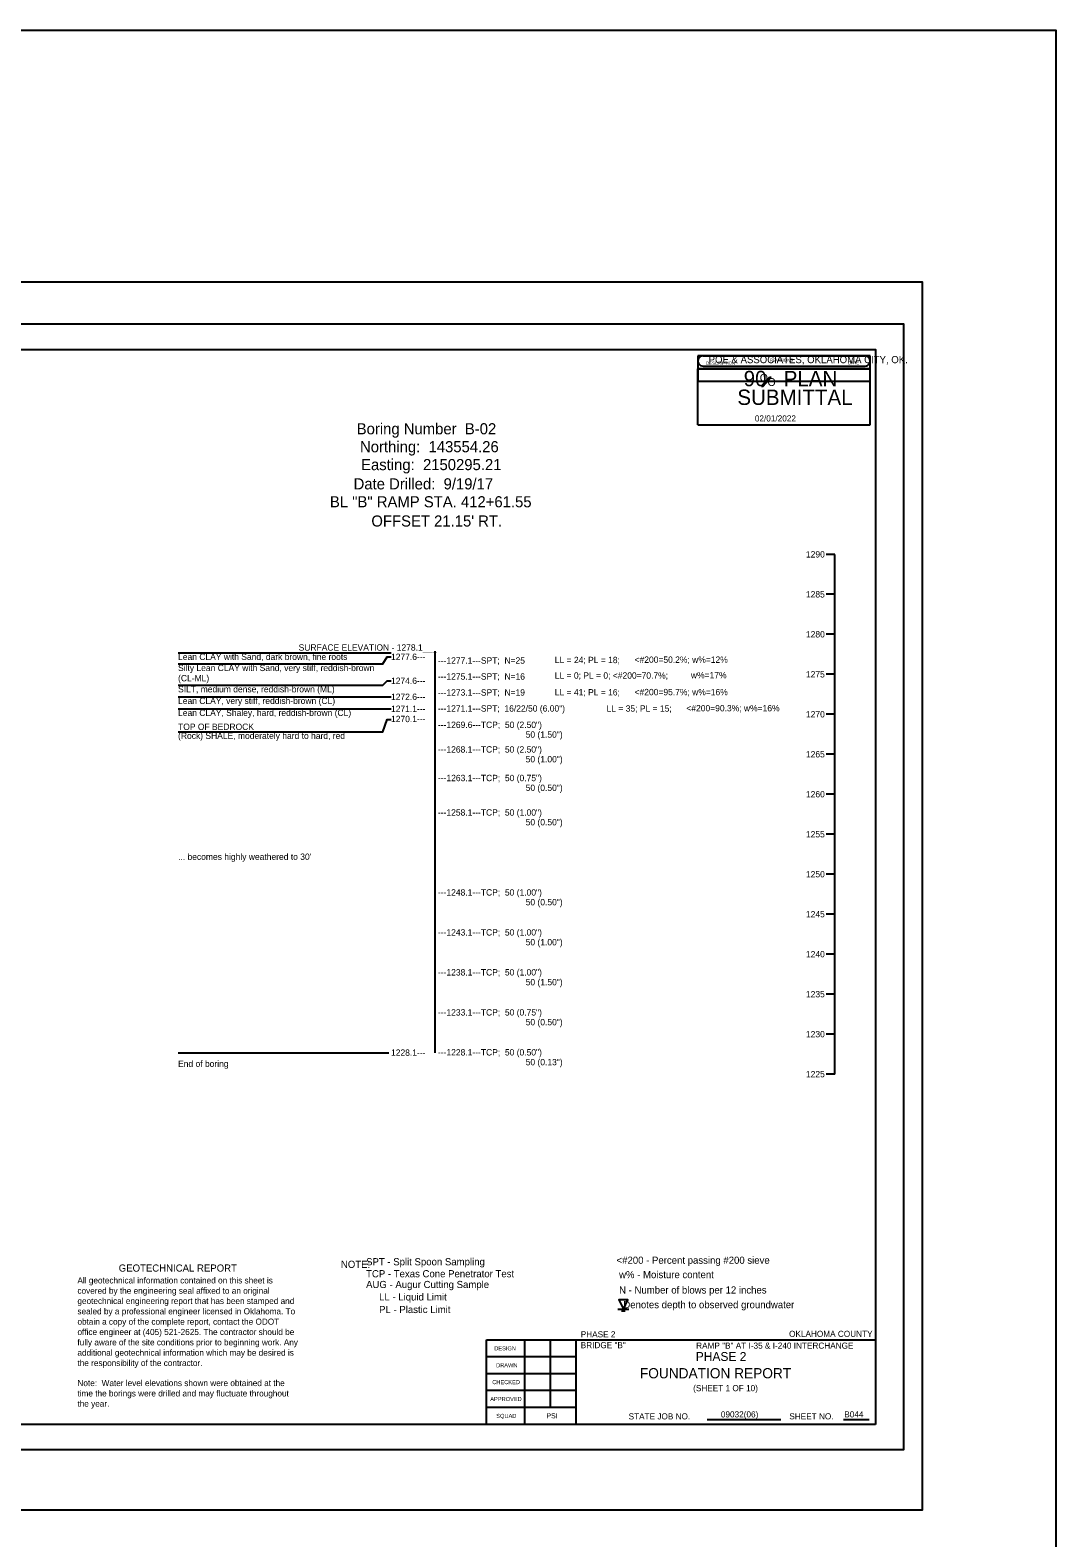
# Model space of a CAD drawing. Extents: x 2150162 to 2150245, y 143729 to 143865.
# Drawn here: x 2150183.36 to 2150203.4, y 143835.6 to 143865.06 of the extents above; entities that cross this region are included whole.
import ezdxf

# ---------------------------------------------------------------- set-up
doc = ezdxf.new("R2010")
doc.units = 0
for name, color, linetype in [('Default', 7, 'Continuous'), ('S', 7, 'Continuous'), ('SHT_Plot_Shape_Full', 7, 'Continuous'), ('SHT_Plot_Shape_Half', 7, 'Continuous'), ('SHT_Sheet_Border', 7, 'Continuous'), ('SHT_Stamp_90_Submit', 7, 'Continuous'), ('SHT_Stamp_Rev_Block', 7, 'Continuous'), ('SHT_Standard_Sheet_Lines', 7, 'Continuous'), ('SHT_Standard_Sheet_Txt', 7, 'Continuous'), ('T', 7, 'Continuous'), ('T-Title', 7, 'Continuous'), ('Text', 7, 'Continuous')]:
    doc.layers.add(name, color=color, linetype=linetype)

# ---------------------------------------------------------------- blocks, each defined once
blk = doc.blocks.new('DGRFC_WTLEV1')
at = {"layer": 'Default'}
for points in [[(-0.0127, 0), (0.0127, 0)], [(0, 0), (0.0106, 0.0212), (-0.0106, 0.0212), (0, 0)], [(-0.0042, -0.0042), (0.0042, -0.0042)]]:
    blk.add_lwpolyline(points, dxfattribs=at)

msp = doc.modelspace()

# ---------------------------------------------------------------- linework, layer by layer
at = {"layer": 'Default'}
for p, q in [((2150199.086, 143844.663), (2150199.086, 143854.819)), ((2150190.373, 143845.074), (2150186.253, 143845.074))]:
    msp.add_line(p, q, dxfattribs=at)
for points in [[(2150199.086, 143854.819), (2150198.919, 143854.819)], [(2150199.086, 143854.038), (2150198.919, 143854.038)], [(2150199.086, 143853.257), (2150198.919, 143853.257)], [(2150186.253, 143852.896), (2150190.419, 143852.896)], [(2150186.253, 143852.679), (2150190.253, 143852.679), (2150190.336, 143852.817), (2150190.419, 143852.817)], [(2150191.27, 143852.924), (2150191.27, 143845.076)], [(2150199.086, 143852.475), (2150198.919, 143852.475)], [(2150186.253, 143852.262), (2150186.419, 143852.262), (2150190.253, 143852.262), (2150190.336, 143852.349), (2150190.419, 143852.349)], [(2150186.253, 143852.036), (2150190.419, 143852.036)], [(2150186.253, 143851.802), (2150190.419, 143851.802)], [(2150186.253, 143851.354), (2150186.419, 143851.354), (2150190.253, 143851.354), (2150190.336, 143851.592), (2150190.419, 143851.592)], [(2150199.086, 143851.694), (2150198.919, 143851.694)], [(2150199.086, 143850.913), (2150198.919, 143850.913)], [(2150199.086, 143850.132), (2150198.919, 143850.132)], [(2150199.086, 143849.35), (2150198.919, 143849.35)], [(2150199.086, 143848.569), (2150198.919, 143848.569)], [(2150199.086, 143847.788), (2150198.919, 143847.788)], [(2150199.086, 143847.007), (2150198.919, 143847.007)], [(2150199.086, 143846.225), (2150198.919, 143846.225)], [(2150199.086, 143845.444), (2150198.919, 143845.444)], [(2150199.086, 143844.663), (2150198.919, 143844.663)]]:
    msp.add_lwpolyline(points, dxfattribs=at)
at = {"layer": 'S'}
msp.add_lwpolyline([(2150203.404, 143784.341), (2150161.568, 143784.341), (2150161.568, 143865.061), (2150203.404, 143865.061)], close=True, dxfattribs=at)
at = {"layer": 'SHT_Plot_Shape_Full'}
msp.add_lwpolyline([(2150164.792, 143860.145), (2150200.792, 143860.145), (2150200.792, 143836.145), (2150164.792, 143836.145)], close=True, dxfattribs=at)
at = {"layer": 'SHT_Plot_Shape_Half'}
msp.add_lwpolyline([(2150166.429, 143859.32), (2150200.429, 143859.32), (2150200.429, 143837.32), (2150166.429, 143837.32)], close=True, dxfattribs=at)
at = {"layer": 'SHT_Sheet_Border'}
for p, q in [((2150192.279, 143837.82), (2150192.279, 143839.47)), ((2150192.279, 143839.47), (2150199.879, 143839.47)), ((2150194.029, 143837.82), (2150194.029, 143839.471))]:
    msp.add_line(p, q, dxfattribs=at)
msp.add_lwpolyline([(2150199.879, 143837.82), (2150168.379, 143837.82), (2150168.379, 143858.82), (2150199.879, 143858.82)], close=True, dxfattribs=at)
at = {"layer": 'SHT_Stamp_90_Submit'}
for p, q in [((2150196.51, 143858.696), (2150199.676, 143858.696)), ((2150196.41, 143858.446), (2150199.776, 143858.446)), ((2150196.41, 143857.347), (2150196.41, 143858.446)), ((2150196.51, 143858.496), (2150199.676, 143858.496)), ((2150197.653, 143858.108), (2150197.809, 143858.281)), ((2150197.671, 143858.108), (2150197.827, 143858.281)), ((2150197.676, 143858.108), (2150197.832, 143858.281)), ((2150197.684, 143858.108), (2150197.839, 143858.281)), ((2150197.809, 143858.281), (2150197.839, 143858.281)), ((2150199.776, 143857.347), (2150199.776, 143858.446)), ((2150197.653, 143858.108), (2150197.684, 143858.108)), ((2150196.41, 143857.347), (2150199.776, 143857.347))]:
    msp.add_line(p, q, dxfattribs=at)
for centre, start, end in [((2150196.51, 143858.596), 89.9952, 270), ((2150199.676, 143858.596), 270, 90.0048)]:
    msp.add_arc(centre, 0.1, start, end, dxfattribs=at)
at = {"layer": 'SHT_Stamp_Rev_Block'}
for p, q in [((2150196.41, 143858.696), (2150196.41, 143858.196)), ((2150199.776, 143858.696), (2150196.41, 143858.696)), ((2150199.776, 143858.196), (2150199.776, 143858.696)), ((2150199.776, 143858.446), (2150196.41, 143858.446)), ((2150199.776, 143858.196), (2150196.41, 143858.196))]:
    msp.add_line(p, q, dxfattribs=at)
at = {"layer": 'SHT_Standard_Sheet_Lines'}
for p, q in [((2150193.029, 143837.82), (2150193.029, 143839.471)), ((2150193.529, 143838.15), (2150193.529, 143839.471)), ((2150196.59, 143837.916), (2150198.03, 143837.917)), ((2150199.255, 143837.916), (2150199.757, 143837.917))]:
    msp.add_line(p, q, dxfattribs=at)
for points in [[(2150194.029, 143839.14), (2150192.279, 143839.14)], [(2150194.029, 143838.81), (2150192.279, 143838.81)], [(2150194.029, 143838.48), (2150192.279, 143838.48)], [(2150194.029, 143838.15), (2150192.279, 143838.15)]]:
    msp.add_lwpolyline(points, dxfattribs=at)

# ---------------------------------------------------------------- block references
at = {"layer": 'Default', "xscale": 8.503919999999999, "yscale": 8.503919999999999}
msp.add_blockref('DGRFC_WTLEV1', (2150194.954, 143840.072), dxfattribs=at)

# ---------------------------------------------------------------- texts
at = {"layer": 'Default'}
for s, height, p in [('Boring Number  B-02', 0.217, (2150189.744, 143857.164)), ('Northing:  143554.26', 0.217, (2150189.808, 143856.814)), ('Easting:  2150295.21', 0.217, (2150189.829, 143856.464)), ('Date Drilled:  9/19/17', 0.217, (2150189.683, 143856.088)), ('BL "B" RAMP STA. 412+61.55', 0.217, (2150189.22, 143855.738)), ("OFFSET 21.15' RT.", 0.217, (2150190.03, 143855.362)), ('1290', 0.124, (2150198.521, 143854.757)), ('1285', 0.124, (2150198.521, 143853.976)), ('1280', 0.124, (2150198.521, 143853.195)), ('SURFACE ELEVATION - 1278.1___', 0.124, (2150188.609, 143852.937)), ('Silty Lean CLAY with Sand, very stiff, reddish-brown', 0.124, (2150186.253, 143852.538)), ('Lean CLAY with Sand, dark brown, fine roots', 0.124, (2150186.253, 143852.755)), ('1277.6---', 0.124, (2150190.414, 143852.755)), ('---1277.1---SPT;  N=25', 0.124, (2150191.331, 143852.683)), ('LL = 24; PL = 18;', 0.124, (2150193.614, 143852.693)), ('<#200=50.2%; w%=12%', 0.124, (2150195.173, 143852.699)), ('(CL-ML)', 0.124, (2150186.253, 143852.338)), ('1274.6---', 0.124, (2150190.414, 143852.287)), ('---1275.1---SPT;  N=16', 0.124, (2150191.331, 143852.371)), ('LL = 0; PL = 0; <#200=70.7%;', 0.124, (2150193.614, 143852.39)), ('w%=17%', 0.124, (2150196.274, 143852.396)), ('1275', 0.124, (2150198.521, 143852.413)), ('SILT, medium dense, reddish-brown (ML)', 0.124, (2150186.253, 143852.122)), ('1272.6---', 0.124, (2150190.414, 143851.974)), ('---1273.1---SPT;  N=19', 0.124, (2150191.331, 143852.058)), ('LL = 41; PL = 16;', 0.124, (2150193.614, 143852.061)), ('<#200=95.7%; w%=16%', 0.124, (2150195.173, 143852.066)), ('Lean CLAY, very stiff, reddish-brown (CL)', 0.124, (2150186.253, 143851.895)), ('Lean CLAY, Shaley, hard, reddish-brown (CL)', 0.124, (2150186.253, 143851.661)), ('1271.1---', 0.124, (2150190.414, 143851.74)), ('---1271.1---SPT;  16/22/50 (6.00")', 0.124, (2150191.331, 143851.746)), ('LL = 35; PL = 15;', 0.124, (2150194.626, 143851.745)), ('<#200=90.3%; w%=16%', 0.124, (2150196.185, 143851.751)), ('TOP OF BEDROCK', 0.124, (2150186.253, 143851.388)), ('1270.1---', 0.124, (2150190.414, 143851.54)), ('---1269.6---TCP;  50 (2.50")', 0.124, (2150191.331, 143851.427)), ('1270', 0.124, (2150198.521, 143851.632)), ('(Rock) SHALE, moderately hard to hard, red', 0.124, (2150186.253, 143851.213)), ('50 (1.50")', 0.124, (2150193.045, 143851.236)), ('---1268.1---TCP;  50 (2.50")', 0.124, (2150191.331, 143850.946)), ('1265', 0.124, (2150198.521, 143850.851)), ('50 (1.00")', 0.124, (2150193.045, 143850.754)), ('---1263.1---TCP;  50 (0.75")', 0.124, (2150191.331, 143850.387)), ('50 (0.50")', 0.124, (2150193.045, 143850.196)), ('1260', 0.124, (2150198.521, 143850.07)), ('---1258.1---TCP;  50 (1.00")', 0.124, (2150191.331, 143849.714)), ('50 (0.50")', 0.124, (2150193.045, 143849.523)), ('1255', 0.124, (2150198.521, 143849.288)), ("... becomes highly weathered to 30'", 0.124, (2150186.253, 143848.849)), ('1250', 0.124, (2150198.521, 143848.507)), ('---1248.1---TCP;  50 (1.00")', 0.124, (2150191.331, 143848.152)), ('50 (0.50")', 0.124, (2150193.045, 143847.961)), ('1245', 0.124, (2150198.521, 143847.726)), ('---1243.1---TCP;  50 (1.00")', 0.124, (2150191.331, 143847.371)), ('50 (1.00")', 0.124, (2150193.045, 143847.179)), ('1240', 0.124, (2150198.521, 143846.945)), ('---1238.1---TCP;  50 (1.00")', 0.124, (2150191.331, 143846.59)), ('50 (1.50")', 0.124, (2150193.045, 143846.398)), ('1235', 0.124, (2150198.521, 143846.163)), ('---1233.1---TCP;  50 (0.75")', 0.124, (2150191.331, 143845.808)), ('50 (0.50")', 0.124, (2150193.045, 143845.617)), ('1230', 0.124, (2150198.521, 143845.382)), ('1228.1---', 0.124, (2150190.414, 143845.021)), ('---1228.1---TCP;  50 (0.50")', 0.124, (2150191.331, 143845.027)), ('End of boring', 0.124, (2150186.253, 143844.804)), ('50 (0.13")', 0.124, (2150193.045, 143844.836)), ('1225', 0.124, (2150198.521, 143844.601))]:
    msp.add_text(s, height=height, dxfattribs=at).set_placement(p)
at = {"layer": 'Defpoints'}
msp.add_text('PHASE 2', height=0.175, dxfattribs=at).set_placement((2150196.369, 143839.058))
at = {"layer": 'SHT_Stamp_90_Submit'}
for s, height, p in [('POE & ASSOCIATES, OKLAHOMA CITY, OK.', 0.14, (2150196.62, 143858.554)), ('90   PLAN', 0.3, (2150197.305, 143858.104)), ('O', 0.153, (2150197.619, 143858.193)), ('O', 0.153, (2150197.771, 143858.109)), ('SUBMITTAL', 0.3, (2150197.181, 143857.738)), ('02/01/2022', 0.12, (2150197.523, 143857.415))]:
    msp.add_text(s, height=height, dxfattribs=at).set_placement(p)
at = {"layer": 'SHT_Stamp_Rev_Block'}
for s, height, p in [('DESCRIPTION', 0.05999, (2150196.57, 143858.525)), ('REVISIONS', 0.06, (2150197.818, 143858.584)), ('DATE', 0.06, (2150199.34, 143858.529))]:
    msp.add_text(s, height=height, dxfattribs=at).set_placement(p)
at = {"layer": 'SHT_Standard_Sheet_Txt'}
for s, height, p in [('DESIGN', 0.08, (2150192.431, 143839.265)), ('DRAWN', 0.08, (2150192.467, 143838.935)), ('CHECKED', 0.08, (2150192.392, 143838.605)), ('APPROVED', 0.08, (2150192.353, 143838.275)), ('SQUAD', 0.08, (2150192.471, 143837.945)), ('STATE JOB NO.', 0.12, (2150195.056, 143837.916)), ('SHEET NO. ', 0.12, (2150198.196, 143837.917))]:
    msp.add_text(s, height=height, dxfattribs=at).set_placement(p)
at = {"layer": 'T'}
for s, height, p in [('PHASE 2', 0.12, (2150194.121, 143839.52)), ('BRIDGE "B"', 0.12, (2150194.121, 143839.308)), ('RAMP "B" AT I-35 & I-240 INTERCHANGE', 0.12, (2150196.376, 143839.298)), ('OKLAHOMA COUNTY', 0.12, (2150198.191, 143839.528)), ('(SHEET 1 OF 10)', 0.12, (2150196.317, 143838.468)), ('PSI', 0.1, (2150193.449, 143837.938)), ('09032(06)', 0.12, (2150196.859, 143837.955)), ('B044', 0.12, (2150199.27, 143837.955))]:
    msp.add_text(s, height=height, dxfattribs=at).set_placement(p)
at = {"layer": 'T-Title'}
msp.add_text('FOUNDATION REPORT', height=0.2, dxfattribs=at).set_placement((2150195.276, 143838.719))
at = {"layer": 'Text'}
for s, height, p in [('GEOTECHNICAL REPORT', 0.14, (2150185.094, 143840.804)), ('NOTE:', 0.14, (2150189.435, 143840.877)), ('    SPT - Split Spoon Sampling', 0.14, (2150189.719, 143840.927)), (' <#200 - Percent passing #200 sieve', 0.14, (2150194.769, 143840.957)), ('All geotechnical information contained on this sheet is ', 0.12, (2150184.287, 143840.573)), ('    AUG - Augur Cutting Sample', 0.14, (2150189.719, 143840.483)), ('    TCP - Texas Cone Penetrator Test', 0.14, (2150189.719, 143840.693)), ('w% - Moisture content', 0.14, (2150194.87, 143840.676)), ('covered by the engineering seal affixed to an original ', 0.12, (2150184.287, 143840.371)), ('geotechnical engineering report that has been stamped and ', 0.12, (2150184.287, 143840.171)), (' LL - Liquid Limit', 0.14, (2150190.129, 143840.24)), ('N - Number of blows per 12 inches', 0.14, (2150194.87, 143840.376)), ('sealed by a professional engineer licensed in Oklahoma. To ', 0.12, (2150184.287, 143839.969)), (' PL - Plastic Limit', 0.14, (2150190.129, 143839.994)), ('    Denotes depth to observed groundwater', 0.14, (2150194.745, 143840.089)), ('obtain a copy of the complete report, contact the ODOT ', 0.12, (2150184.287, 143839.767)), ('fully aware of the site conditions prior to beginning work. Any ', 0.12, (2150184.287, 143839.363)), ('office engineer at (405) 521-2625. The contractor should be ', 0.12, (2150184.287, 143839.565)), ('additional geotechnical information which may be desired is ', 0.12, (2150184.287, 143839.161)), ('the responsibility of the contractor.', 0.12, (2150184.287, 143838.959)), ('Note:  Water level elevations shown were obtained at the ', 0.12, (2150184.287, 143838.567)), ('time the borings were drilled and may fluctuate throughout ', 0.12, (2150184.287, 143838.365)), ('the year.', 0.12, (2150184.287, 143838.165))]:
    msp.add_text(s, height=height, dxfattribs=at).set_placement(p)

doc.saveas('drawing.dxf')
